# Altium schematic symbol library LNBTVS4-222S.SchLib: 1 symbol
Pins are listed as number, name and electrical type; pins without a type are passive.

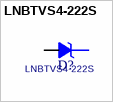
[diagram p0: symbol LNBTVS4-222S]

## LNBTVS4-222S
designator D?
footprint ST_SMC
pins: 1 K, 2 A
